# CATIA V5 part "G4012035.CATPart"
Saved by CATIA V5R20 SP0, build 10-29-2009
Part number: G4012035
Revision: 4
Definition: design
Nomenclature: G4012035
Source: made
Description: NOT SPECIFIED
Bounding box of the stored display mesh (mm): x 0 to 35, y -16 to 16, z -16 to 16
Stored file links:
  C:\Users\Raffaele\Desktop\3D X SITO CF\BOLEX\25-BUSH REF 401\G4012035.CATPart
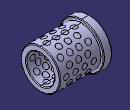
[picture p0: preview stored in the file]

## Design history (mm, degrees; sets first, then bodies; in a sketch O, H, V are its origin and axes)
Body1 "MANIFOLD_SOLID_BREP #8105" (main body)
  Solid1: solid without history
Body2 "MANIFOLD_SOLID_BREP #8252"
  Solid2: solid without history
Body3 "MANIFOLD_SOLID_BREP #8399"
  Solid3: solid without history
Body4 "MANIFOLD_SOLID_BREP #8546"
  Solid4: solid without history
Body5 "MANIFOLD_SOLID_BREP #8693"
  Solid5: solid without history
Body6 "MANIFOLD_SOLID_BREP #8842"
  Solid6: solid without history
Body7 "MANIFOLD_SOLID_BREP #8991"
  Solid7: solid without history
Body8 "MANIFOLD_SOLID_BREP #9140"
  Solid8: solid without history
Body9 "MANIFOLD_SOLID_BREP #9289"
  Solid9: solid without history
Body10 "MANIFOLD_SOLID_BREP #9438"
  Solid10: solid without history
Body11 "MANIFOLD_SOLID_BREP #9587"
  Solid11: solid without history
Body12 "MANIFOLD_SOLID_BREP #9736"
  Solid12: solid without history
Body13 "MANIFOLD_SOLID_BREP #9885"
  Solid13: solid without history
Body14 "MANIFOLD_SOLID_BREP #10034"
  Solid14: solid without history
Body15 "MANIFOLD_SOLID_BREP #10183"
  Solid15: solid without history
Body16 "MANIFOLD_SOLID_BREP #10332"
  Solid16: solid without history
Body17 "MANIFOLD_SOLID_BREP #10481"
  Solid17: solid without history
Body18 "MANIFOLD_SOLID_BREP #10630"
  Solid18: solid without history
Body19 "MANIFOLD_SOLID_BREP #10779"
  Solid19: solid without history
Body20 "MANIFOLD_SOLID_BREP #10928"
  Solid20: solid without history
Body21 "MANIFOLD_SOLID_BREP #11077"
  Solid21: solid without history
Body22 "MANIFOLD_SOLID_BREP #11226"
  Solid22: solid without history
Body23 "MANIFOLD_SOLID_BREP #11375"
  Solid23: solid without history
Body24 "MANIFOLD_SOLID_BREP #11524"
  Solid24: solid without history
Body25 "MANIFOLD_SOLID_BREP #11673"
  Solid25: solid without history
Body26 "MANIFOLD_SOLID_BREP #11822"
  Solid26: solid without history
Body27 "MANIFOLD_SOLID_BREP #11971"
  Solid27: solid without history
Body28 "MANIFOLD_SOLID_BREP #12120"
  Solid28: solid without history
Body29 "MANIFOLD_SOLID_BREP #12269"
  Solid29: solid without history
Body30 "MANIFOLD_SOLID_BREP #12418"
  Solid30: solid without history
Body31 "MANIFOLD_SOLID_BREP #12567"
  Solid31: solid without history
Body32 "MANIFOLD_SOLID_BREP #12716"
  Solid32: solid without history
Body33 "MANIFOLD_SOLID_BREP #12865"
  Solid33: solid without history
Body34 "MANIFOLD_SOLID_BREP #13012"
  Solid34: solid without history
Body35 "MANIFOLD_SOLID_BREP #13159"
  Solid35: solid without history
Body36 "MANIFOLD_SOLID_BREP #13308"
  Solid36: solid without history
Body37 "MANIFOLD_SOLID_BREP #13457"
  Solid37: solid without history
Body38 "MANIFOLD_SOLID_BREP #13606"
  Solid38: solid without history
Body39 "MANIFOLD_SOLID_BREP #13755"
  Solid39: solid without history
Body40 "MANIFOLD_SOLID_BREP #13904"
  Solid40: solid without history
Body41 "MANIFOLD_SOLID_BREP #14053"
  Solid41: solid without history
Body42 "MANIFOLD_SOLID_BREP #14202"
  Solid42: solid without history
Body43 "MANIFOLD_SOLID_BREP #14351"
  Solid43: solid without history
Body44 "MANIFOLD_SOLID_BREP #14500"
  Solid44: solid without history
Body45 "MANIFOLD_SOLID_BREP #14649"
  Solid45: solid without history
Body46 "MANIFOLD_SOLID_BREP #14798"
  Solid46: solid without history
Body47 "MANIFOLD_SOLID_BREP #14947"
  Solid47: solid without history
Body48 "MANIFOLD_SOLID_BREP #15096"
  Solid48: solid without history
Body49 "MANIFOLD_SOLID_BREP #15243"
  Solid49: solid without history
Body50 "MANIFOLD_SOLID_BREP #15390"
  Solid50: solid without history
Body51 "MANIFOLD_SOLID_BREP #15539"
  Solid51: solid without history
Body52 "MANIFOLD_SOLID_BREP #15688"
  Solid52: solid without history
Body53 "MANIFOLD_SOLID_BREP #15837"
  Solid53: solid without history
Body54 "MANIFOLD_SOLID_BREP #15986"
  Solid54: solid without history
Body55 "MANIFOLD_SOLID_BREP #16135"
  Solid55: solid without history
Body56 "MANIFOLD_SOLID_BREP #16284"
  Solid56: solid without history
Body57 "MANIFOLD_SOLID_BREP #16433"
  Solid57: solid without history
